(* Logix 5000 project; controller MVI69MNET vendor 1 type 14 code 65 rev 16.3; software revision 16.04 *)

TASK MainTask (continuous, watchdog 500 ms) : MainProgram

MODULES
   Controller : vendor 1 type 14 code 65 (CompactLogixL35Controller 0, rev 16.3)
      LocalENB : 1769-L35E Ethernet Port (CompactLogixL35Ethernet 1, rev 16.3)
      Local : CompactBus (CompactVirtualAdapter 3, rev 16.3, Input RPI 5 ms)
         MVI69MNET : 1769-MODULE (Compact 1, rev 1.1, Output RPI 2 ms)
END_MODULES

TYPE MNETBlockStats :   // This object is used to store the block transfer statistics for the MVI69-MNet module.
STRUCT
   Read : INT;   // Total number of read block transfers
   Write : INT;   // Total number of write block transfers
   Parse : INT;   // Total number of blocks parsed
   Event : INT;   // Total number of event blocks received
   Cmd : INT;   // Total number of command blocks received
   Err : INT;   // Total number of block transfer errors
END_STRUCT
END_TYPE

TYPE MNETCmdControl :
STRUCT
   CmdControlTrigger : BOOL;
   CmdControlPending : BOOL;
   CommandIndex : INT[6];
   CmdsAddedToQueue : INT;
   NumberOfCommands : INT;
   CmdControlBlockID : INT;
END_STRUCT
END_TYPE

TYPE MNETCoilArray :   // Conversion to INT Values
STRUCT
   Boolean : BOOL[416];   // Description from B
END_STRUCT
END_TYPE

TYPE MNETCONFIG :
STRUCT
   BlockTransferSize : INT;
END_STRUCT
END_TYPE

TYPE MNETConnectionInput :
STRUCT
   Data : INT[62];
END_STRUCT
END_TYPE

TYPE MNETConnectionOutput :
STRUCT
   Data : INT[61];
END_STRUCT
END_TYPE

TYPE MNETCONTROL :
STRUCT
   BootTimer : TIMER;
   ColdBoot : BOOL;
   WarmBoot : BOOL;
   ResetStatus : BOOL;   // Reset Status
   EventCmd : MNETEventCmd;
   CmdControl : MNETCmdControl;
   PassThru : MNETPassThru;
END_STRUCT
END_TYPE

TYPE MNETDATA :
STRUCT
   ReadData : INT[600];
   WriteData : INT[600];
END_STRUCT
END_TYPE

TYPE MNETEventCmd :
STRUCT
   EventCmdTrigger : BOOL;
   EventCmdPending : BOOL;
   IPaddress : INT[4];
   ServicePort : INT;
   NodeAddress : INT;
   InternalAddress : INT;
   Count : INT;
   Swap : INT;
   FunctionCode : INT;
   DeviceDBaddress : INT;
   EventCmdStatusReturned : INT;
   EventBlockID : INT;
END_STRUCT
END_TYPE

TYPE MNETModuleDef :
STRUCT
   CONFIG : MNETCONFIG;
   DATA : MNETDATA;
   STATUS : MNETSTATUS;   // Status information in each read block
   CONTROL : MNETCONTROL;
   UTIL : MNETUTIL;
END_STRUCT
END_TYPE

TYPE MNETPassThru :
STRUCT
   MBControl1 : CONTROL;
   MBControl2 : CONTROL;
   MBOffsetByte : INT;
   MBOffsetBit : DINT;
   MBMsgLen : INT;
   MBMsg : SINT[500];
   MBScratch : INT[3];
   ByteLength : INT;
   MBMaskedVal : DINT;
   MBWordAddress : DINT;
   MBBitAddress : DINT;
   MBdouble : DINT;
   MBCoil : MNETCoilArray;
END_STRUCT
END_TYPE

TYPE MNETPortStats :   // This object is used to store the port statistics for an MVI69-MNet port.
STRUCT
   CmdReq : INT;   // Total number of command list requests sent
   CmdResp : INT;   // Total number of command list responses received
   CmdErr : INT;   // Total number of command list errors
   Requests : INT;   // Total number of requests for port
   Responses : INT;   // Total number of responses for port
   ErrSent : INT;   // Total number of errors sent
   ErrRec : INT;   // Total number of errors received
   CfgErrWord : INT;   // Configuration Error Word
   CurErr : INT;   // Current Error code
   LastErr : INT;   // Last recorded error code
END_STRUCT
END_TYPE

TYPE MNETSTATUS :   // This status data is returned on each read block and can be used to detect proper module operation.
STRUCT
   PassCnt : INT;   // Program cycle counter
   Block : MNETBlockStats;   // Block transfer statistics
   MnetServer : MNETPortStats;   // MNet server status data
   MBAPServer : MNETPortStats;   // MBAP server status data
   ClientStatus : MNETPortStats;   // Client status data
END_STRUCT
END_TYPE

TYPE MNETUTIL :
STRUCT
   ReadDataSizeGet : INT;   // Gets ReadData Array Length.
   WriteDataSizeGet : INT;   // Gets WriteData Array Length.
   ReadDataBlkCount : INT;   // holds the value of the Block Counts of the Read Data Array.
   WriteDataBlkCount : INT;   // holds the value of the Block Counts of the Write Data Array.
   RBTSremainder : INT;   // The remainder of the 60, 120 or 240 block to transfer.
   WBTSremainder : INT;   // The remainder of the 60, 120 or 240 block to transfer.
   LastRead : INT;
   LastWrite : INT;
   BlockIndex : INT;
END_STRUCT
END_TYPE

ADD_ON_INSTRUCTION AOI69MNET   (* revision 1.6 *)
// Add On instruction interface between the CompactLogix backplane and the MVI69-MNET module.
// Revision note:
// v1.6 - Changed Block 9958 function to avoid Minor Overflow Fault occurring on bit16 of every word transmitted from WriteData[ ]
// Help:
// v1.6 - Changed Block 9958 function to avoid Minor Overflow Fault occurring on bit16 of every word transmitted from WriteData[ ]
// v1.4 - Added Block 9997 function to reset status
// No Add-On functionality change.
// The revision level was updated to reflect the rung import change  which replaced the COP instruction by CPS for data integrity.
VAR_IN_OUT
   Connection_Input : MNETConnectionInput; {required}
   Connection_Output : MNETConnectionOutput; {required}
   MNET : MNETModuleDef; {required}
END_VAR

ROUTINE Logic   (* ladder *)
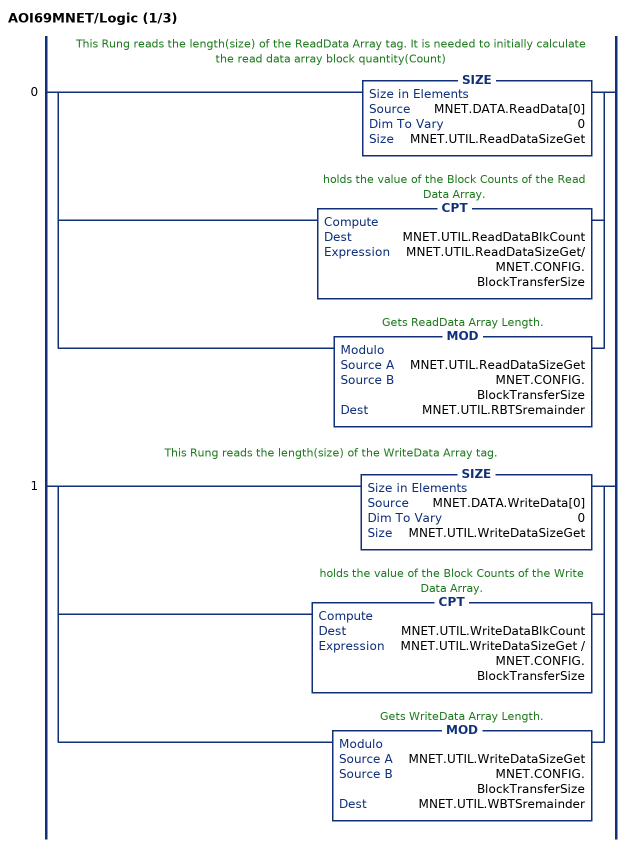
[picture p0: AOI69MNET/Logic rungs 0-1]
   // This Rung reads the length(size) of the ReadData Array tag. It is needed to initially calculate the read data array block quantity(Count)
   0: [SIZE(MNET.DATA.ReadData[0],0,MNET.UTIL.ReadDataSizeGet) ,CPT(MNET.UTIL.ReadDataBlkCount,MNET.UTIL.ReadDataSizeGet/MNET.CONFIG.BlockTransferSize) ,MOD(MNET.UTIL.ReadDataSizeGet,MNET.CONFIG.BlockTransferSize,MNET.UTIL.RBTSremainder) ];
   // This Rung reads the length(size) of the WriteData Array tag.
   1: [SIZE(MNET.DATA.WriteData[0],0,MNET.UTIL.WriteDataSizeGet) ,CPT(MNET.UTIL.WriteDataBlkCount,MNET.UTIL.WriteDataSizeGet / MNET.CONFIG.BlockTransferSize) ,MOD(MNET.UTIL.WriteDataSizeGet,MNET.CONFIG.BlockTransferSize,MNET.UTIL.WBTSremainder) ];
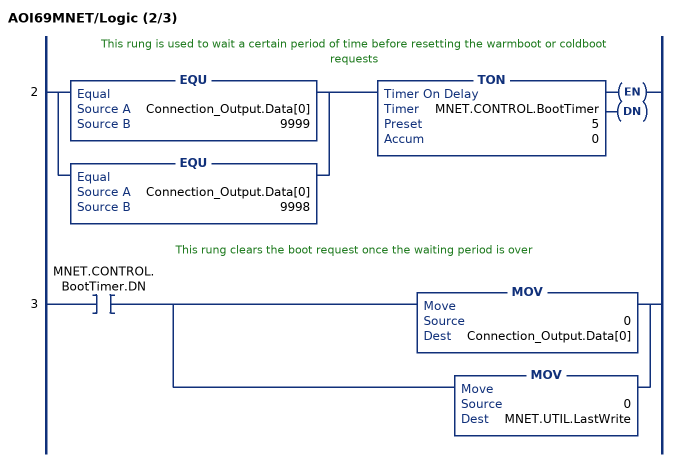
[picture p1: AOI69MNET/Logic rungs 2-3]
   // This rung is used to wait a certain period of time before resetting the warmboot or coldboot requests
   2: [EQU(Connection_Output.Data[0],9999) ,EQU(Connection_Output.Data[0],9998) ]TON(MNET.CONTROL.BootTimer,5,0);
   // This rung clears the boot request once the waiting period is over
   3: XIC(MNET.CONTROL.BootTimer.DN)[MOV(0,Connection_Output.Data[0]) ,MOV(0,MNET.UTIL.LastWrite) ];
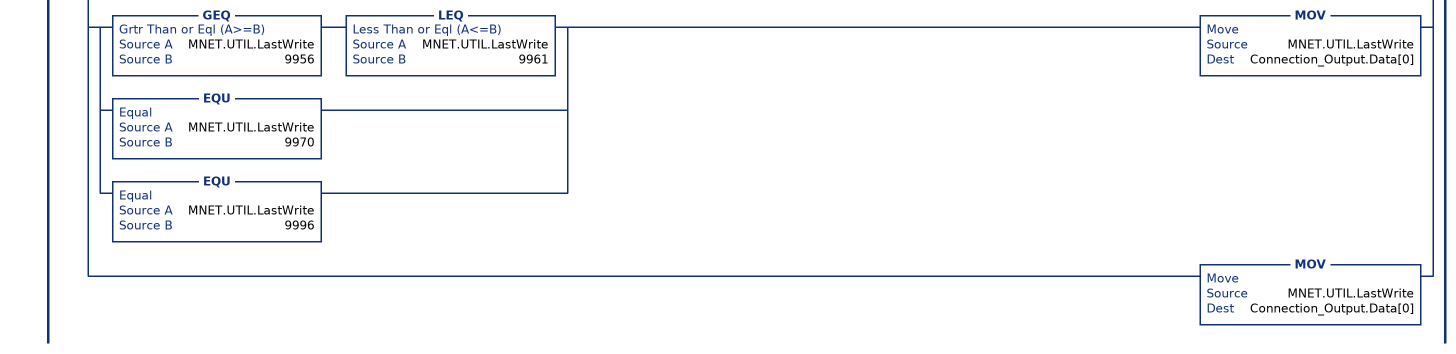
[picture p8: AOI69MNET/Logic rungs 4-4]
   // The routines will only be scanned once the processor receives a new read block ID from the module
   4: NEQ(MNET.UTIL.LastRead,Connection_Input.Data[0])[MOV(Connection_Input.Data[0],MNET.UTIL.LastRead) ,GEQ(MNET.UTIL.LastRead,1) [LEQ(MNET.UTIL.LastRead,MNET.UTIL.ReadDataBlkCount) [CPT(MNET.UTIL.BlockIndex,(MNET.UTIL.LastRead - 1) * MNET.CONFIG.BlockTransferSize) ,COP(Connection_Input.Data[2],MNET.DATA.ReadData[MNET.UTIL.BlockIndex],MNET.CONFIG.BlockTransferSize) ] ,CMP(MNET.UTIL.LastRead - MNET.UTIL.ReadDataBlkCount = 1) GRT(MNET.UTIL.RBTSremainder,0) [CPT(MNET.UTIL.BlockIndex,(MNET.UTIL.LastRead - 1) * MNET.CONFIG.BlockTransferSize) ,COP(Connection_Input.Data[2],MNET.DATA.ReadData[MNET.UTIL.BlockIndex],MNET.UTIL.RBTSremainder) ] ] ,[EQU(MNET.UTIL.LastRead,-1) ,EQU(MNET.UTIL.LastRead,0) ] [COP(Connection_Input.Data[2],MNET.STATUS.PassCnt,1) ,COP(Connection_Input.Data[3],MNET.STATUS.Block.Read,6) ,COP(Connection_Input.Data[19],MNET.STATUS.MnetServer.CmdReq,10) ,COP(Connection_Input.Data[29],MNET.STATUS.MBAPServer.CmdReq,10) ,COP(Connection_Input.Data[39],MNET.STATUS.ClientStatus.CmdReq,10) ] ,EQU(MNET.UTIL.LastRead,2000) [MOV(MNET.UTIL.LastRead,MNET.CONTROL.EventCmd.EventBlockID) ,MOV(Connection_Input.Data[2],MNET.CONTROL.EventCmd.EventCmdStatusReturned) ,OTU(MNET.CONTROL.EventCmd.EventCmdPending) ,OTU(MNET.CONTROL.EventCmd.EventCmdTrigger) ] ,LIM(5001,MNET.UTIL.LastRead,5006) [MOV(MNET.UTIL.LastRead,MNET.CONTROL.CmdControl.CmdControlBlockID) ,MOV(Connection_Input.Data[2],MNET.CONTROL.CmdControl.CmdsAddedToQueue) ,OTU(MNET.CONTROL.CmdControl.CmdControlPending) ,OTU(MNET.CONTROL.CmdControl.CmdControlTrigger) ] ,EQU(9996,MNET.UTIL.LastRead) [MOV(Connection_Input.Data[2],MNET.CONTROL.PassThru.MBMsgLen) ,COP(Connection_Input.Data[3],MNET.CONTROL.PassThru.MBMsg[0],MNET.CONTROL.PassThru.MBMsgLen) ] ,LIM(9956,MNET.UTIL.LastRead,9957) LES(Connection_Input.Data[3],600) [MOV(Connection_Input.Data[3],MNET.CONTROL.PassThru.MBOffsetByte) ,COP(Connection_Input.Data[4],MNET.DATA.WriteData[MNET.CONTROL.PassThru.MBOffsetByte],Connection_Input.Data[2]) ] ,EQU(9958,MNET.UTIL.LastRead) MVM(Connection_Input.Data[3],16#0000FFFF,MNET.CONTROL.PassThru.MBMaskedVal) LES(MNET.CONTROL.PassThru.MBMaskedVal,65535) [DIV(MNET.CONTROL.PassThru.MBMaskedVal,16,MNET.CONTROL.PassThru.MBWordAddress) MOD(MNET.CONTROL.PassThru.MBMaskedVal,16,MNET.CONTROL.PassThru.MBBitAddress) ,MOV(Connection_Input.Data[4],MNET.CONTROL.PassThru.MBScratch[2]) ,NEQ(MNET.CONTROL.PassThru.MBScratch[2],0) OTL(MNET.DATA.WriteData[MNET.CONTROL.PassThru.MBWordAddress].[MNET.CONTROL.PassThru.MBBitAddress]) ,EQU(MNET.CONTROL.PassThru.MBScratch[2],0) OTU(MNET.DATA.WriteData[MNET.CONTROL.PassThru.MBWordAddress].[MNET.CONTROL.PassThru.MBBitAddress]) ] ,EQU(9959,MNET.UTIL.LastRead) [MOV(Connection_Input.Data[3],MNET.CONTROL.PassThru.MBOffsetByte) ,MOV(Connection_Input.Data[2],MNET.CONTROL.PassThru.MBControl1.LEN) ,MOV(Connection_Input.Data[2],MNET.CONTROL.PassThru.MBControl2.LEN) ,FAL(MNET.CONTROL.PassThru.MBControl1,10,0,ALL,MNET.DATA.WriteData[MNET.CONTROL.PassThru.MBOffsetByte+MNET.CONTROL.PassThru.MBControl1.POS],MNET.DATA.WriteData[MNET.CONTROL.PassThru.MBOffsetByte+MNET.CONTROL.PassThru.MBControl1.POS] AND(NOT Connection_Input.Data[34+MNET.CONTROL.PassThru.MBControl1.POS])) ,FAL(MNET.CONTROL.PassThru.MBControl2,10,0,ALL,MNET.DATA.WriteData[MNET.CONTROL.PassThru.MBOffsetByte+MNET.CONTROL.PassThru.MBControl2.POS],MNET.DATA.WriteData[MNET.CONTROL.PassThru.MBOffsetByte+MNET.CONTROL.PassThru.MBControl2.POS] OR(Connection_Input.Data[4+MNET.CONTROL.PassThru.MBControl2.POS] AND Connection_Input.Data[4+MNET.CONTROL.PassThru.MBControl2.POS])) ] ,EQU(9961,MNET.UTIL.LastRead) [MOV(Connection_Input.Data[2],MNET.CONTROL.PassThru.MBMsgLen) ,CPT(MNET.CONTROL.PassThru.MBMsgLen,MNET.CONTROL.PassThru.MBMsgLen * 2 + 2) ,COP(Connection_Input.Data[3],MNET.CONTROL.PassThru.MBMsg[0],MNET.CONTROL.PassThru.MBMsgLen) ] ,MOV(Connection_Input.Data[1],MNET.UTIL.LastWrite) ,XIC(MNET.CONTROL.ColdBoot) [NEQ(MNET.UTIL.LastWrite,9999) ,NEQ(Connection_Output.Data[0],9999) ] [MOV(9999,MNET.UTIL.LastWrite) ,OTU(MNET.CONTROL.ColdBoot) ] ,XIC(MNET.CONTROL.WarmBoot) [MOV(9998,MNET.UTIL.LastWrite) ,OTU(MNET.CONTROL.WarmBoot) ] ,XIC(MNET.CONTROL.ResetStatus) [MOV(9997,MNET.UTIL.LastWrite) ,OTU(MNET.CONTROL.ResetStatus) ] ,GEQ(MNET.UTIL.LastWrite,1) [LEQ(MNET.UTIL.LastWrite,MNET.UTIL.WriteDataBlkCount) [CPT(MNET.UTIL.BlockIndex,(MNET.UTIL.LastWrite - 1) * MNET.CONFIG.BlockTransferSize) ,COP(MNET.DATA.WriteData[MNET.UTIL.BlockIndex],Connection_Output.Data[1],MNET.CONFIG.BlockTransferSize) ] ,CMP(MNET.UTIL.LastWrite - MNET.UTIL.WriteDataBlkCount = 1) GRT(MNET.UTIL.WBTSremainder,0) [CPT(MNET.UTIL.BlockIndex,(MNET.UTIL.LastWrite-1)*MNET.CONFIG.BlockTransferSize) ,COP(MNET.DATA.WriteData[MNET.UTIL.BlockIndex],Connection_Output.Data[1],MNET.UTIL.WBTSremainder) ] ] ,LIM(1000,MNET.UTIL.LastWrite,1083) [CPT(MNET.UTIL.BlockIndex,(MNET.UTIL.LastWrite - 1000) * MNET.CONFIG.BlockTransferSize) ,COP(MNET.DATA.ReadData[MNET.UTIL.BlockIndex],Connection_Output.Data[1],MNET.CONFIG.BlockTransferSize) ] ,XIC(MNET.CONTROL.EventCmd.EventCmdTrigger) XIO(MNET.CONTROL.EventCmd.EventCmdPending) [COP(MNET.CONTROL.EventCmd.IPaddress[0],Connection_Output.Data[1],11) ,MOV(2000,MNET.UTIL.LastWrite) ,OTL(MNET.CONTROL.EventCmd.EventCmdPending) ] ,XIC(MNET.CONTROL.CmdControl.CmdControlTrigger) XIO(MNET.CONTROL.CmdControl.CmdControlPending) [COP(MNET.CONTROL.CmdControl.CommandIndex[0],Connection_Output.Data[1],6) ,LIM(1,MNET.CONTROL.CmdControl.NumberOfCommands,6) ADD(5000,MNET.CONTROL.CmdControl.NumberOfCommands,MNET.UTIL.LastWrite) ,OTL(MNET.CONTROL.CmdControl.CmdControlPending) ] ,[EQU(-1,MNET.UTIL.LastWrite) ,EQU(0,MNET.UTIL.LastWrite) ] MOV(MNET.UTIL.LastWrite,Connection_Output.Data[0]) ,[GEQ(MNET.UTIL.LastWrite,9956) LEQ(MNET.UTIL.LastWrite,9961) ,EQU(MNET.UTIL.LastWrite,9970) ,EQU(MNET.UTIL.LastWrite,9996) ] MOV(MNET.UTIL.LastWrite,Connection_Output.Data[0]) ,MOV(MNET.UTIL.LastWrite,Connection_Output.Data[0]) ];
END_ROUTINE
END_ADD_ON_INSTRUCTION

VAR_GLOBAL   (* controller tags *)
   AOI69MNET : AOI69MNET;
   Connection_Input : MNETConnectionInput := (Data[0] := 1, Data[1] := 6);
   Connection_Output : MNETConnectionOutput := (Data[0] := 9);
   MNET : MNETModuleDef;
   Test1 : BOOL;
END_VAR

PROGRAM MainProgram   (* main routine MainRoutine *)

ROUTINE MainRoutine   (* ladder *)
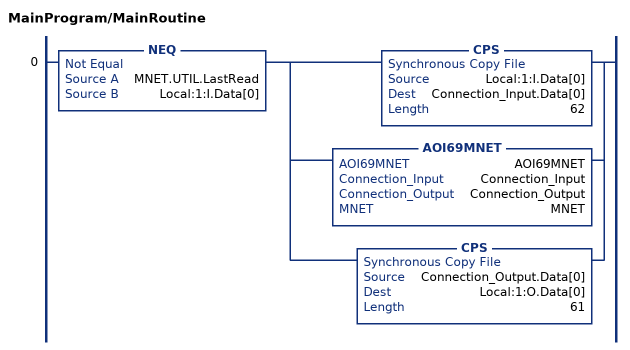
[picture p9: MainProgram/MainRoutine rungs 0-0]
   0: NEQ(MNET.UTIL.LastRead,Local:1:I.Data[0])[CPS(Local:1:I.Data[0],Connection_Input.Data[0],62) ,AOI69MNET(AOI69MNET,Connection_Input,Connection_Output,MNET) ,CPS(Connection_Output.Data[0],Local:1:O.Data[0],61) ];
END_ROUTINE
END_PROGRAM
